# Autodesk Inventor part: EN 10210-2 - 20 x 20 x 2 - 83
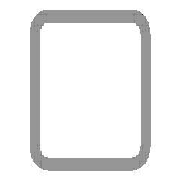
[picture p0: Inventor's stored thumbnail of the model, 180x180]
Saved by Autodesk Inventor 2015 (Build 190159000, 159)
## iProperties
Created: 2015-05
Part Number: EN 10210-2 - 20 x 20 x 2 - 83
Material: Steel, Mild
Description: Tube
Document SubType Name: Modeling
Standard: DIN
Designer: TREINA6
Standard Revision: 1997
Standards Organization: DIN
Language: en-US
Size Designation: 20 x 20 x 2
Categories: <MemberInstance><Categories><Category DisplayName="Structural Shapes" InternalName="089c4875-fa83-4c05-b084-43b9cc11f5ed" Mnemonic="GRDR"><CategoryParameter Dis
Stock Number: 20 x 20 x 2
Density: 7.85 g/cm^3
Appearance: Semi-Polished
IsCustomPart: 1
_CCFamilyMember: 1
_CCFamilyDisplayName: DIN EN 10210-2 (Square) - Tube
_FrameMemberDoc: Frame Member File
_Version: 15.0.0
_GetPNFromCC: 1
Author: TREINA6
G_L: 83,000 mm
G_W: 20,000 mm
G_H: 20,000 mm
+A4C977E4-CD73-45EE-B01C-96E779B5DB59+CUTDETAIL1: Cut
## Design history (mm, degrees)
node "Start plane"
node "End plane"
sketch "Sketch"
  geometry: L1 (-10, -7)-(-10, 7); L2 (-7, 10)-(7, 10); L3 (10, 7)-(10, -7); L4 (7, -10)-(-7, -10); L5 (-7, 8)-(7, 8); L6 (8, 7)-(8, -7); L7 (7, -8)-(-7, -8); L8 (-8, -7)-(-8, 7); L9 (0, 14.87)-(0, -14.87) reference; L10 (-14.87, 0)-(14.87, 0) reference; A1 r 3 centre (-7, -7) between (-10, -7) and (-7, -10); A2 r 3 centre (-7, 7) between (-7, 10) and (-10, 7); A3 r 3 centre (7, 7) between (10, 7) and (7, 10); A4 r 3 centre (7, -7) between (7, -10) and (10, -7); A5 r 1 centre (-7, 7) between (-7, 8) and (-8, 7); A6 r 1 centre (7, 7) between (8, 7) and (7, 8); A7 r 1 centre (7, -7) between (7, -8) and (8, -7); A8 r 1 centre (-7, -7) between (-8, -7) and (-7, -8)
  constraints: 16 end point, 16 point on circle, 8 centre point, 8 tangent, 4 parallel, 3 equal radius, 2 perpendicular, 7 other
  dimensions: "d7" = 3 radius of A1 (= G_IR); "d10" = 20 distance between parallel lines of L2 L4 (= G_H); "d11" = 20 distance between parallel lines of L1 L3 (= G_W); "d12" = 2 distance between parallel lines of L3 L6 (= G_T); "d15" = 10 distance between parallel lines of L2 L10 (= 0.5 x d10); "d16" = 10 distance between parallel lines of L9 L3 (= 0.5 x d11)
extrude "Body" new body sketch "Sketch" stored distance "d3" = 83 (= G_L); taper "d4" = 0 deg
node "Driven Length"
  sketch "Sketch3"
    geometry: L1 (0, 0)-(10, 0) reference
    constraints: 2 end point, 1 horizontal
  workplane "Work Plane3"
  sketch "Sketch4"
    geometry: L1 (-2, 20)-(12, 20) reference; L2 (-2, 103)-(12, 103) reference
    dimensions: "d18" = 83 distance between parallel lines of L1 L2 (derived)
workplane "Work Plane4"
split "Split1"
body "Solid1"
other parameters: "G_W" = 20 [user parameter; used in 1 equation term], "G_H" = 20 [user parameter; used in 1 equation term], "G_T" = 2 [user parameter; used in 1 equation term], "G_IR" = 3 [user parameter; used in 1 equation term], "G_L" = 83 (= d18) [user parameter; used in 1 equation term], "G_OFFSET_END" = 0 [user parameter; used in 1 equation term], "d14" = 103 (= G_OFFSET_END + B_L), "B_L" = 103 [user parameter; used in 1 equation term], "d17" = 90 deg
